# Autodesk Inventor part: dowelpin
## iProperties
Author: cdotson
Shininess: 86.0
PropertySet Name: _Private Model Information
Created: 2001-01
Part Number: dowelpin
Document SubType Name: Modeling
Designer: cdotson
Material: Steel, High Strength Low Alloy
Control State: 0
Master: False
Checked Out: False
PropertySet Name: Design Tracking Control
Density: 7.84
Volumn: 0.006002562836700406
Area: 0.1828214805794355
PropertySet Name: Model Information
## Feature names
1. Extrusion1
2. Fillet1
3. Chamfer2
